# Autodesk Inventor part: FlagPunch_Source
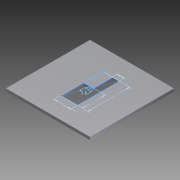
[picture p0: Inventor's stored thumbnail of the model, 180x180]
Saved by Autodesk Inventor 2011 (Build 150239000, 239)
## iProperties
Created: 2007-02
Part Number: FlagPunch_Source
Material: Default
Document SubType Name: Sheet Metal
Designer: Autodesk, Inc.
Mass: 0.8338 g
Surface Area: 18.296 cm^2
Volume: 0.8338 cm^3
Density: 1 g/cm^3
Flat Pattern Width: 3 cm
Flat Pattern Length: 3 cm
Flat Pattern Area: 9 cm^2
Sheet Metal Rule: 1 mm
Sheet Metal Width: 30.000 mm
Sheet Metal Length: 30.000 mm
Sheet Metal Area: 900.000 mm^2
Author: Autodesk, Inc.
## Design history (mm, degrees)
node "Face1"
  sketch "Sketch1"
    geometry: L1 (-15, 15)-(15, 15); L2 (15, 15)-(15, -15); L3 (15, -15)-(-15, -15); L4 (-15, -15)-(-15, 15); L5 (-15, 15)-(15, -15); 2 further points
    constraints: 10 end point, 2 parallel, 1 coincident, 1 horizontal, 1 midpoint, 1 perpendicular
    dimensions: "d0" = 30 distance of L2.end L3.end; "d1" = 30 distance of L1.end L2.end (= d0)
sketch "Sketch2"
  geometry: L1 (-3, -7.5)-(3, -7.5); L2 (3, -7.5)-(3, 0.7); L3 (3, 0.7)-(-3, 0.7); L4 (-3, 0.7)-(-3, -7.5); L5 (3, -7.5)-(0.5, -7.5); L6 (0.5, -7.5)-(0.5, 7.5); L7 (0.5, 7.5)-(3, 7.5); L8 (3, 7.5)-(3, -7.5); L9 (-3, -7.5)-(3, 7.5); 3 further points
  constraints: 18 end point, 4 parallel, 2 coincident, 2 horizontal, 2 perpendicular, 1 midpoint
  dimensions: "d10" = 6 distance of L1.start L1.end; "d11" = 15 distance between parallel lines of L1 L7; "d12" = 8.2 distance of L1.end L2.end; "d13" = 2.5 distance of L6.end L7.end
cut "Cut1" sketch "Sketch2" dims "d3" = 1 (= Thickness), "d4" = 0
body "Solid1"
sketch "Sketch3"
  geometry: L1 (-3, 7.5)-(3, 7.5); L2 (3, 7.5)-(3, -7.5); L3 (3, -7.5)-(-3, -7.5); L4 (-3, -7.5)-(-3, 7.5); L5 (-3, -7.5)-(3, 7.5); L6 (-3, 7.5)-(0.5, 7.5); L7 (0.5, 7.5)-(0.5, 0.7); L8 (0.5, 0.7)-(-3, 0.7); L9 (-3, 0.7)-(-3, 7.5); L10 (1.25, -0.722)-(-1.25, -0.722); L11 (-1.25, -0.722)-(0, 1.443); L12 (0, 1.443)-(1.25, -0.722); 4 further points
  constraints: 24 end point, 4 parallel, 3 coincident, 3 horizontal, 2 perpendicular, 1 midpoint, 7 other
  dimensions: "d14" = 15 distance of L3.end L1.start; "d15" = 6 distance of L2.end L3.end; "d16" = 8.2 distance between parallel lines of L3 L8; "d17" = 2.5 distance between parallel lines of L2 L7; "d18" = 2.5 distance of L10.start L10.end
face "Plate1" dims "Thickness" = 1
feature "Definition1" dims "d0" = 1 (derived)
other parameters: "BendRadius" = 0.5, "BendReliefWidth" = 1 (= Thickness), "BendReliefDepth" = 0.5 (= 0.5 x Thickness), "CornerReliefSize" = 4 (= 4 x Thickness), "SeamGap" = 0.01, "MinimumRemnant" = 2 (= 2 x Thickness), "TransitionRadius" = 0.5 (= BendRadius), "JacobiRadiusSize" = 1 (= Thickness), "d2" = 0.5 (= BendRadius), "GapSize" = 1 (= Thickness), "BendRadius" = 0.5, "BendReliefDepth" = 0.5, "BendReliefWidth" = 1, "CornerReliefSize" = 4, "JacobiRadiusSize" = 1, "MinimumRemnant" = 2, "Thickness" = 1, "TransitionRadius" = 0.5, "GapSize" = 1
